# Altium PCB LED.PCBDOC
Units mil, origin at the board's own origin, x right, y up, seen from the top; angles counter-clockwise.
Board outline 6000 x 4000 mil, 2 copper layers (Top Layer, Bottom Layer); 12 components, 28 nets, 64 pads, 6 vias.
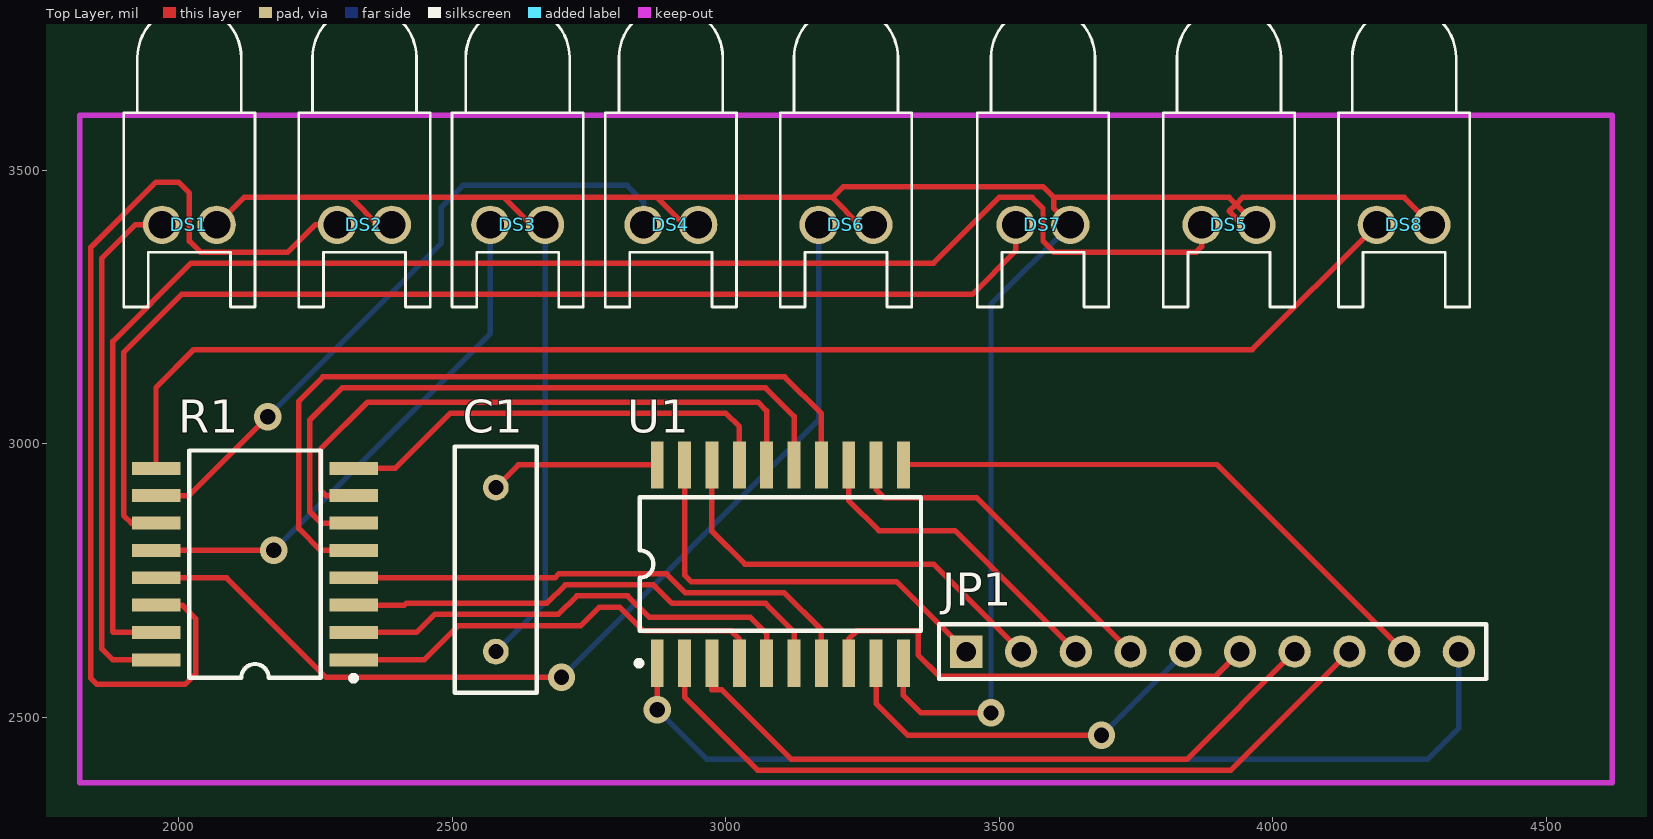
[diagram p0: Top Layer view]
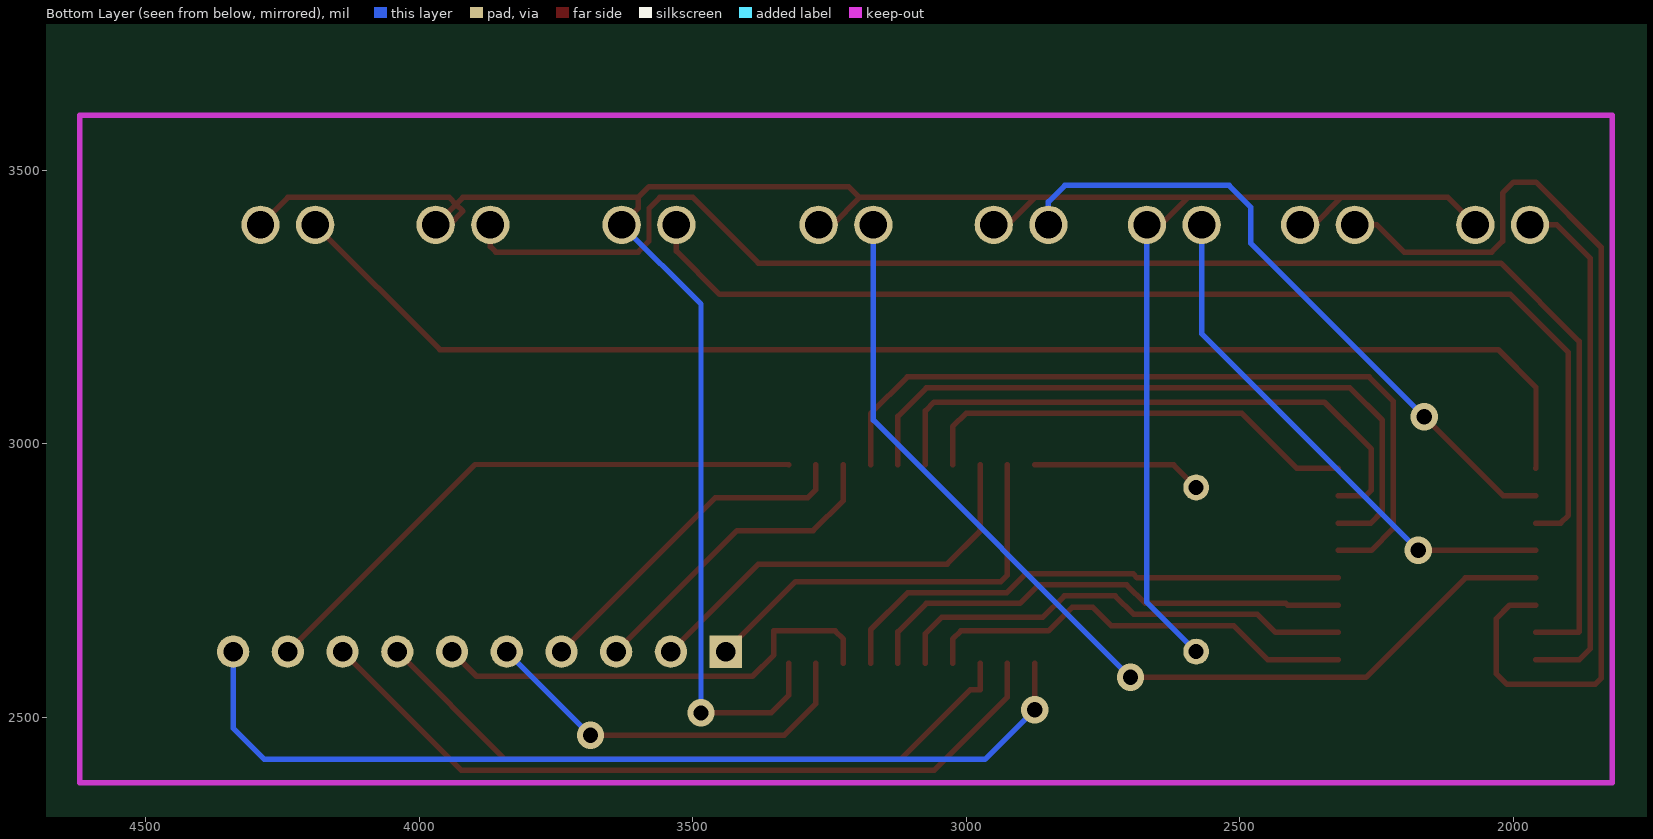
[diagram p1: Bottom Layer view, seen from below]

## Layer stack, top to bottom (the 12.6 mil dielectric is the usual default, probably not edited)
Top Layer: signal copper 1.4
Dielectric: dielectric 12.6, FR-4, Dk 4.8
Bottom Layer: signal copper 1.4

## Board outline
1000,1000 7000,1000 7000,5000 1000,5000

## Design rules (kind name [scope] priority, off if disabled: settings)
Clearance [All] p1: gap=10
ComponentClearance [All] p1: gap=10 collisioncheckmode=0
PolygonConnect [All] p1: connectstyle=Relief reliefconductorwidth=10 reliefentries=4 polygonreliefangle="90 Angle"
RoutingLayers [All] p1: top layer=Horizontal bottom layer=Vertical
RoutingVias [All] p1: holewidth=28 width=50 viastyle="Through Hole" minholewidth=28 minwidth=50 maxholewidth=28 maxwidth=50
SolderMaskExpansion [All] p1: expansion=4
TestPointUsage [All] p1: valid=0 allowmultiple=FALSE
Testpoint [All] p1: side=15 testpointundercomponent=TRUE minsize=40 maxsize=100 preferedsize=60 minholesize=0 maxholesize=40 preferedholesize=32 testpointgrid=1 style=1023 order=-539222988
Width [All] p1: maxlimit=10 minlimit=10 preferedwidth=10
16 further rules are at their usual default settings.

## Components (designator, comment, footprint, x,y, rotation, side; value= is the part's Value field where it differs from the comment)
C1 "0.1uF" RAD-0.3 2580,2620 r90 top
DS1 "LED0" LED-0 2020,3400 r180 top
DS2 "LED0" LED-0 2340,3400 r180 top
DS3 "LED0" LED-0 2620,3400 r180 top
DS4 "LED0" LED-0 2900,3400 r180 top
DS5 "LED0" LED-0 3920,3400 r180 top
DS6 "LED0" LED-0 3220,3400 r180 top
DS7 "LED0" LED-0 3580,3400 r180 top
DS8 "LED0" LED-0 4240,3400 r180 top
JP1 "Header 10" HDR1X10 3440,2620 r0 top
R1 "330" SO-G16/G6.9 2140,2780 r90 top
U1 "TPIC6B273DW" SO-G20 3100,2780 r0 top

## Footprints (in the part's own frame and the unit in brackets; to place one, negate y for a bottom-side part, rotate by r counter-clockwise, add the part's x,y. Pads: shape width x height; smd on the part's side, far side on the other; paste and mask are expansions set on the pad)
HDR1X10 [mm]
  rect 1.5x1.5 hole 0.9: 1(0,0)
  round 1.5 hole 0.9: 2(2.54,0) 3(5.08,0) 4(7.62,0) 5(10.16,0) 6(12.7,0) 7(15.24,0) 8(17.78,0) 9(20.32,0) 10(22.86,0)
  silkscreen extent -1.27,-1.27 24.13,1.27
LED-0 [mil]
  round 70 hole 50: 1(50,0) 2(-50,0)
  silkscreen extent -120,-400 120,150
RAD-0.3 [mm]
  round 1.2 hole 0.7: 1(0,0) 2(7.62,0)
  silkscreen extent -1.91,-1.91 9.53,1.91
SO-G16/G6.9 [mm]
  rect 0.6x2.25 smd: 1(-4.445,-4.575) 2(-3.175,-4.575) 3(-1.905,-4.575) 4(-0.635,-4.575) 5(0.635,-4.575) 6(1.905,-4.575) 7(3.175,-4.575) 8(4.445,-4.575) 9(4.445,4.575) 10(3.175,4.575) 11(1.905,4.575) 12(0.635,4.575) 13(-0.635,4.575) 14(-1.905,4.575) 15(-3.175,4.575) 16(-4.445,4.575)
  silkscreen extent -5.42,-4.7 5.28,3.05
SO-G20 [mm]
  rect 0.6x2.2 smd: 1(-5.715,-4.6) 2(-4.445,-4.6) 3(-3.175,-4.6) 4(-1.905,-4.6) 5(-0.635,-4.6) 6(0.635,-4.6) 7(1.905,-4.6) 8(3.175,-4.6) 9(4.445,-4.6) 10(5.715,-4.6) 11(5.715,4.6) 12(4.445,4.6) 13(3.175,4.6) 14(1.905,4.6) 15(0.635,4.6) 16(-0.635,4.6) 17(-1.905,4.6) 18(-3.175,4.6) 19(-4.445,4.6) 20(-5.715,4.6)
  silkscreen extent -6.69,-4.72 6.53,3.1

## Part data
C1: library part Cap, "Capacitor"
DS1 DS2 DS3 DS4 DS5 DS6 DS7 DS8: "Typical INFRARED GaAs LED"
JP1: "Header, 10-Pin"
R1: library part "Res Pack3", "Resistor Array"
U1: "Power Logic Octal D-Type Latch"

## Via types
v1: diameter 50, hole 28, Top Layer to Bottom Layer, 6 vias

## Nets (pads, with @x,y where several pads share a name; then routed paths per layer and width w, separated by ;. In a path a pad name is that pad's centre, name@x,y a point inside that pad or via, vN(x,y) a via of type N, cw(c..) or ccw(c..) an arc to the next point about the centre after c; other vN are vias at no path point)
GND: C1.1 DS1.2 DS2.2 DS3.2 DS4.2 DS5.2 DS6.2 DS7.2 DS8.2 U1.10 | length 4866.2
  Top Layer w10: DS1.2 2120,3450 2315,3450 ; DS2.2 2365,3400 2315,3450 ; DS3.2 2645,3400 2595,3450 ; DS4.2 2925,3400 2875,3450 ; DS6.2 3245,3400 3195,3450 ; U1.10 3325,2540 3357,2508 v1(3485,2508) ; DS7.2 3600,3430 3600,3450 ; DS8.2 4240,3450 3945,3450 3932.5,3437.5 ; 2315,3450 2595,3450 ; 2595,3450 2875,3450 ; 2875,3450 3195,3450 ; 3195,3450 3215,3470 3580,3470 3600,3450 ; 3600,3450 3920,3450 3932.5,3437.5 ; 3932.5,3437.5 3920,3425 3945,3400 DS5.2 3932.5,3437.5
  Bottom Layer w10: C1.1 2670,2710 DS3.2 ; v1(3485,2508) 3485,3255 DS7.2
NetDS1_1: DS1.1 R1.16 | length 957.4
  Top Layer w10: R1.16 1880,2605 1860,2625 1860,3339 1921,3400 DS1.1
NetDS2_1: DS2.1 R1.14 | length 1799.9
  Top Layer w10: R1.14 2007,2705 2032,2680 2032,2580 2012,2560 1851,2560 1840,2571 1840,3359 1959,3478 2000,3478 2020,3458 2020,3370 2040,3350 2200,3350 2250,3400 DS2.1
NetDS3_1: DS3.1 R1.12 | length 973.1
  Top Layer w10: R1.12 v1(2174,2805)
  Bottom Layer w10: v1(2174,2805) 2570,3201 DS3.1
NetDS4_1: DS4.1 R1.10 | length 1218.1
  Top Layer w10: R1.10 2019,2905 v1(2163,3049)
  Bottom Layer w10: v1(2163,3049) 2480,3366 2480,3432 2520,3472 2820,3472 2850,3442 DS4.1
NetDS5_1: DS5.1 R1.15 | length 2830.9
  Top Layer w10: R1.15 1881,2655 1880,2656 1880,3187 2023,3330 3380,3330 3500,3450 3560,3450 3580,3430 3580,3370 3600,3350 3860,3350 3870,3360 DS5.1
NetDS6_1: DS6.1 R1.13 | length 1837.2
  Top Layer w10: R1.13 2088,2755 2270,2573 v1(2700,2573)
  Bottom Layer w10: v1(2700,2573) 3170,3043 DS6.1
NetDS7_1: DS7.1 R1.11 | length 2118.3
  Top Layer w10: R1.11 1914,2855 1900,2869 1900,3167 2006,3273 3451,3273 3530,3352 DS7.1
NetDS8_1: DS8.1 R1.9 | length 2502.9
  Top Layer w10: R1.9 1959,2955 1959,3103 2028,3172 3962,3172 DS8.1
NetJP1_1: JP1.1 U1.19 | length 774.1
  Top Layer w10: U1.19 2925,2760 2937,2748 3312,2748 JP1.1
NetJP1_2: JP1.2 U1.18 | length 777.2
  Top Layer w10: U1.18 2975,2840 3035,2780 3380,2780 JP1.2
NetJP1_3: JP1.3 U1.13 | length 594.4
  Top Layer w10: U1.13 3225,2896 3280,2841 3419,2841 JP1.3
NetJP1_4: JP1.4 U1.12 | length 632.7
  Top Layer w10: U1.12 3275,2916 3290,2901 3459,2901 JP1.4
NetJP1_5: JP1.5 U1.9 | length 726.3
  Top Layer w10: U1.9 3275,2525 3333,2467 v1(3687,2467)
  Bottom Layer w10: v1(3687,2467) JP1.5
NetJP1_6: JP1.6 U1.8 | length 844.1
  Top Layer w10: U1.8 3225,2643 3240,2658 3352,2658 3352,2614 3391,2575 3895,2575 JP1.6
NetJP1_7: JP1.7 U1.3 | length 1248.1
  Top Layer w10: U1.3 2975,2550 2993,2550 3120,2423 3843,2423 JP1.7
NetJP1_8: JP1.8 U1.2 | length 1422.3
  Top Layer w10: U1.2 2925,2537 3059,2403 3923,2403 JP1.8
NetJP1_9: JP1.9 U1.11 | length 1057.6
  Top Layer w10: U1.11 3325,2962 3898,2962 JP1.9
NetJP1_10: JP1.10 U1.1 | length 1751.2
  Top Layer w10: v1(2875,2514) U1.1
  Bottom Layer w10: v1(2875,2514) 2966,2423 4283,2423 4340,2480 JP1.10
NetR1_1: R1.1 U1.4 | length 812.8
  Top Layer w10: R1.1 2449,2605 2511,2667 2735,2667 2769,2701 2807,2701 2850,2658 3010,2658 3025,2643 U1.4
NetR1_2: R1.2 U1.5 | length 865.3
  Top Layer w10: R1.2 2435,2655 2468,2688 2694,2688 2728,2722 2821,2722 2860,2683 3045,2683 3075,2653 U1.5
NetR1_3: R1.3 U1.6 | length 912.9
  Top Layer w10: R1.3 2413,2705 2416,2708 2673.07,2708 2707.07,2742 2868,2742 2902,2708 3073,2708 3125,2656 U1.6
NetR1_4: R1.4 U1.7 | length 961.1
  Top Layer w10: R1.4 2688,2755 2695,2762 2892,2762 2926,2728 3107,2728 3175,2660 U1.7
NetR1_5: R1.5 U1.14 | length 1444.6
  Top Layer w10: R1.5 2260,2805 2220,2845 2220,3078 2264,3122 3108,3122 3175,3055 U1.14
NetR1_6: R1.6 U1.15 | length 1275.7
  Top Layer w10: R1.6 2261,2855 2240,2876 2240,3043 2299,3102 3073,3102 3125,3050 U1.15
NetR1_7: R1.7 U1.16 | length 1095.4
  Top Layer w10: R1.7 2270,2905 2260,2915 2260,2990 2346,3076 3059,3076 3075,3060 U1.16
NetR1_8: R1.8 U1.17 | length 827
  Top Layer w10: R1.8 2396,2955 2497,3056 3000,3056 3025,3031 U1.17
VCC: C1.2 U1.20 | length 312
  Top Layer w10: C1.2 2621.1,2961.1 U1.20

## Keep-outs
Keep-Out Layer:
  lines w10: 1820,2380 1820,3600 4620,3600 4620,2380 1820,2380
